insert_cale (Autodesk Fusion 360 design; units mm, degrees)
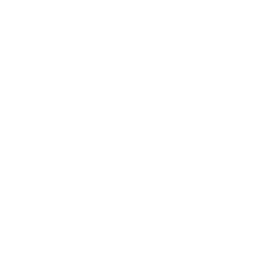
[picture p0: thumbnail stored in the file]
part number: 2026-02-03-16-09-23-272
sketch "Sketch1" plane through (0, 0, 0) normal (0, 1, 0) x axis (1, 0, 0)
  line L1 (10, 0) -> (0, 0)
  line L2 (0, -10) -> (0, 0)
  line L3 (9.7071, -0.2929) -> (0.2929, -9.7071)
  line L4 (16, 0) -> (10.4142, 0)
  line L5 (16, -36) -> (16, 0)
  line L6 (0, -36) -> (16, -36)
  line L7 (0, -10.4142) -> (0, -36)
  line L8 (16, -15) -> (16, 0)
  line L9 (10, -36) -> (0, -36)
  line L10 (10, -17) -> (10, -36)
  line L11 (15, -16) -> (11, -16)
  arc A1 centre (1, -10.4142) radius 1 clockwise from (0, -10.4142) to (0.2929, -9.7071)
  arc A2 centre (10.4142, -1) radius 1 clockwise from (9.7071, -0.2929) to (10.4142, 0)
  arc A3 centre (11, -17) radius 1 clockwise from (10, -17) to (11, -16)
  arc A4 centre (15, -15) radius 1 clockwise from (16, -15) to (15, -16)
  point P1 (0, 0)
  point P2 (0, 0)
  point P4 (0, 0)
  point P9 (16, -16)
  point P10 (10, -36)
  point P5 (0, -10)
  point P3 (10, 0)
  point P6 (16, 0)
  point P7 (16, -36)
  point P8 (0, -36)
  coincident P1 P2
  horizontal L1
  coincident P1 P4
  perpendicular L1 L2
  parallel L1 L4
  perpendicular L4 L5
  perpendicular L2 L6
  perpendicular L6 L7
  coincident L5 P9
  coincident L6 P10
  perpendicular L6 L10
  perpendicular L10 L11
  coincident P5 L7
  coincident P5 L3
  tangent L7 A1
  tangent L3 A1
  coincident P3 L3
  coincident P3 L4
  tangent L3 A2
  tangent L4 A2
  equal A1 A2
  tangent L10 A3
  tangent L11 A3
  equal A1 A3
  coincident P9 L11
  coincident P9 L8
  tangent L11 A4
  tangent L8 A4
  equal A1 A4
  dimension "d67" distance P2 P3 = 10
  dimension "d68" distance P4 P5 = 10
  dimension "d69" distance P3 P6 = 6
  dimension "d70" distance P6 P7 = 36
  dimension "d71" distance P6 P9 = 16
  dimension "d72" distance P8 P10 = 10
  dimension "d73" radius A1 = 1
extrude "Extrude1" new body sketch "Sketch1" profile of L3 L4 L5 L6 L7 L10 L11 A1 A2 A3 A4 along normal blind 10
sketch "Sketch2" plane through (0, 0, 36) normal (0, 0, 1) x axis (-1, 0, 0)
  line L1 (-10, 0) -> (0, 0)
  line L2 (-10, -10) -> (-10, 0)
  line L3 (0, -10) -> (-10, -10)
  line L4 (0, 0) -> (0, -10)
  line L5 (0, 0) -> (-10, -10)
  line L6 (0, -10) -> (-10, 0)
  line L7 (-3, -3) -> (-7, -3)
  line L8 (-3, -7) -> (-3, -3)
  line L9 (-7, -7) -> (-3, -7)
  line L10 (-7, -3) -> (-7, -7)
  line L11 (-3, -7) -> (-7, -3)
  line L12 (-7, -7) -> (-3, -3)
  point P4 (-10, -10)
  point P6 (-10, -10)
  point P1 (0, 0)
  point P7 (0, 0)
  point P3 (-10, 0)
  point P8 (-10, 0)
  point P5 (0, -10)
  point P9 (0, -10)
  point P14 (-5, -5)
  point P12 (-3, -7)
  point P13 (-7, -7)
  point P11 (-3, -3)
  coincident P4 P6
  coincident P1 P7
  coincident P3 P8
  coincident P5 P9
  horizontal L7
  perpendicular L7 L8
  parallel L7 L9
  parallel L8 L10
  coincident L11 P14
  coincident L12 P14
  midpoint L6 P14
  dimension "d77" distance P12 P13 = 4
  dimension "d78" distance P11 P12 = 4
joint_origin "JointOrigin2" OffsetX 0 OffsetY 0 OffsetZ 0 AngleZ 0
extrude "Extrude2" add sketch "Sketch2" profile of L7 L8 L9 L10 along normal blind 3
chamfer "Chamfer1" distance 0.6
